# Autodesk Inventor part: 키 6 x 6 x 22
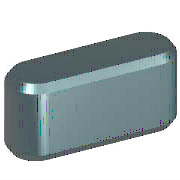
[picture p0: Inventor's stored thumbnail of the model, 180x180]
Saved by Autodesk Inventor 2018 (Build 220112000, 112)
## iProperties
IsCustomPart: 1
Created: 2012-02
Part Number: 키 6 x 6 x 22
Material: 강철, 연강
Description: 키 및 해당 키홈
Document SubType Name: Modeling
Standard: KS B 1311
Designer: mduedu
Standards Organization: KS
Language: ko-KR
Size Designation: 6 x 6 x 22
Categories: <MemberInstance><Categories><Category DisplayName="샤프트 부품" InternalName="7f7aeb1f-a693-4053-b835-cee3144e0d98" Mnemonic="SHFT"><Category DisplayName="키" Interna
Density: 7.86 g/cm^3
Mass: 5.79788 g
Surface Area: 5.294 cm^2
Volume: 0.737644 cm^3
Appearance: 노란색
Author: mduedu
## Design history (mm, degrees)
workplane "Work Plane1"
workplane "Work Plane2"
sketch "스케치1"
  geometry: L1 (3, 3)-(19, 3); L2 (19, -3)-(3, -3); L3 (0, 9.4)-(0, -7.4) reference; L4 (-5, 0)-(30, 0) reference; L5 (22, 0)-(22, 7); A1 r 3 centre (3, 0) between (3, 3) and (3, -3); A2 r 3 centre (19, 0) between (19, -3) and (19, 3)
  constraints: 6 end point, 5 point on circle, 4 tangent, 3 point on line, 2 centre point, 1 horizontal, 1 parallel, 1 perpendicular
  dimensions: "d0" = 3 radius of A1 (= 0.5 x PB); "d13" = 3 radius of A2 (= 0.5 x PB); "d14" = 22 distance between parallel lines of L5 L3 (= NLG)
extrude "본체1" new body sketch "스케치1" taper "d3" = 0 deg; stored distance "d4" = 10
workplane "Work Plane3"
body "Solid1"
chamfer "모따기1" distance "d8" = 0.4 (= PHH); stored, may be unused: second distance "d9" = 0.4 (= PHH), angle "d15" = 45 deg
other parameters: "d1" = -3.5 (= -PNT), "d2" = 2.5 (= PH - PNT), "NLG" = 22 [user parameter; used in 3 equation terms], "PB" = 6 [user parameter; used in 2 equation terms], "PNT" = 3.5 [user parameter; used in 2 equation terms], "PH" = 6 [user parameter; used in 1 equation term], "PHH" = 0.4 [user parameter; used in 2 equation terms], "d10" = 0, "d16" = 0, "d17" = 0, "d18" = 0, "WDMIN" = 17 [user parameter], "PLB2" = 22 (= NLG) [user parameter], "WDMAX" = 22 [user parameter], "PLB1" = 22 (= NLG) [user parameter], "RR" = 0.16 [user parameter], "PUEB" = 2.8 [user parameter]
